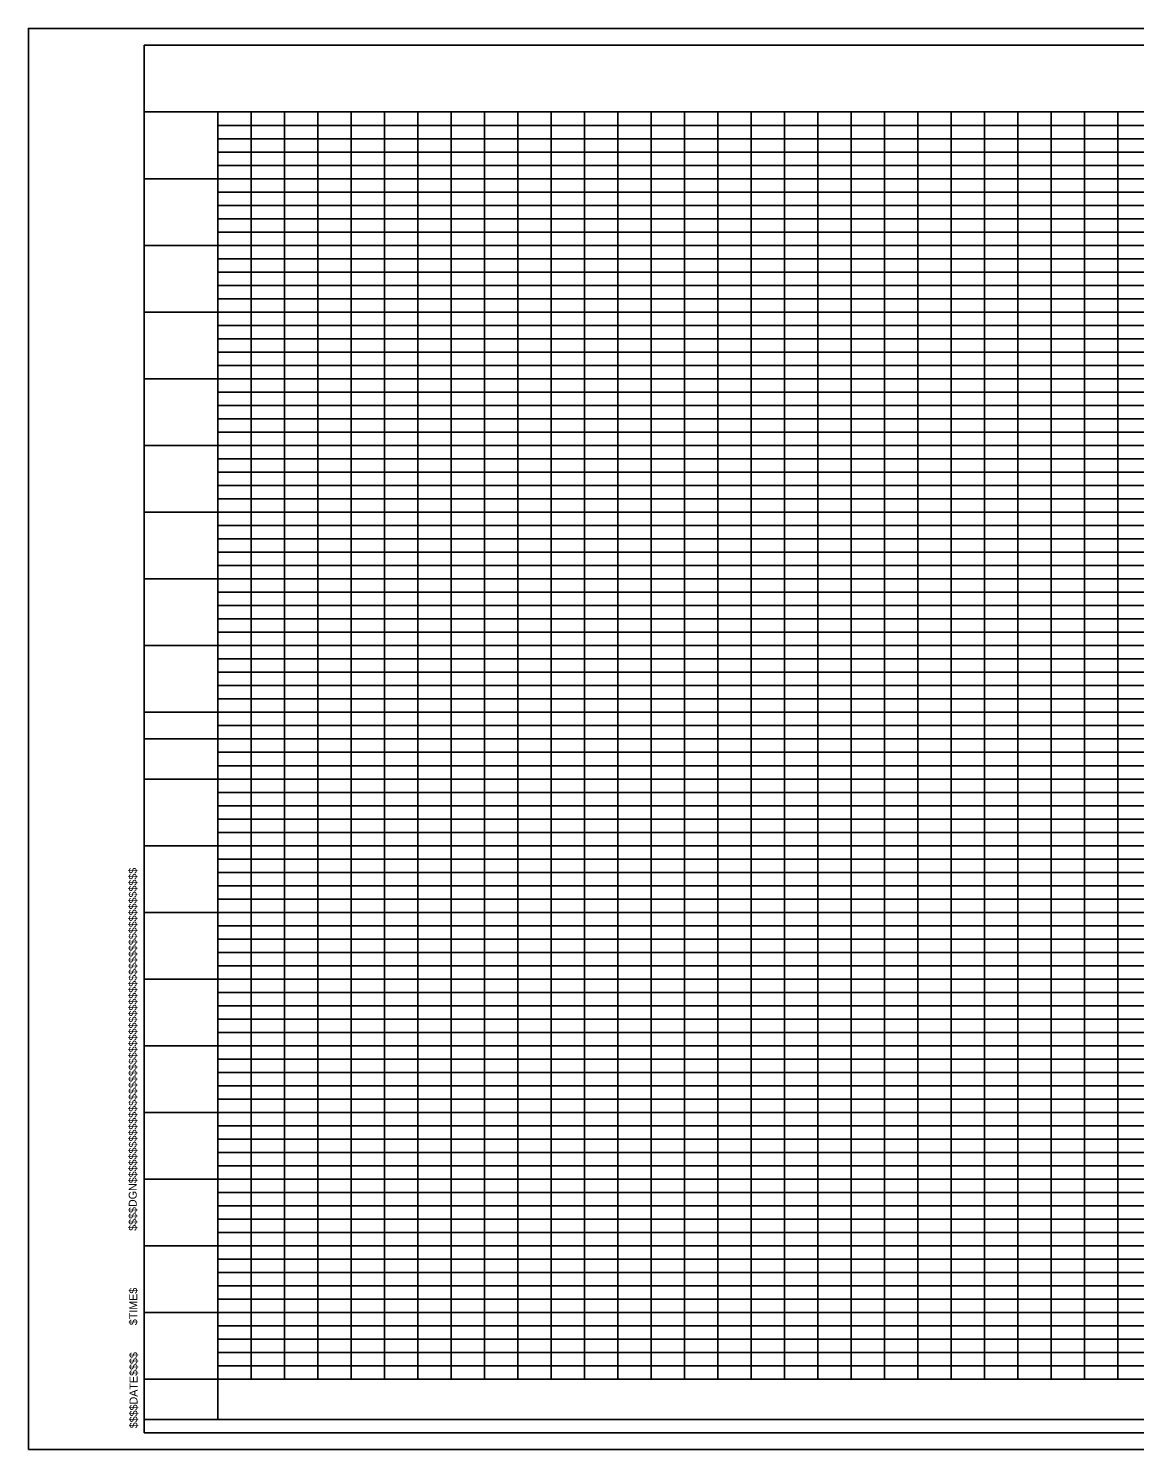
# Model space of a CAD drawing. Extents: x -87 to 2484, y -13 to 1056.
# Drawn here: x -87 to 742, y -13 to 1053 of the extents above; entities that cross this region are included whole.
import ezdxf

# ---------------------------------------------------------------- set-up
doc = ezdxf.new("R2010")
doc.units = 0
for name, color, linetype in [('D_CFL_Clip_Boundary_1', 7, 'Continuous'), ('D_CFL_Clip_Boundary_2', 7, 'Continuous'), ('D_CFL_Sheet_Border_ PlotShape', 7, 'Continuous'), ('D_CFL_Sheet_Border_Base', 7, 'Continuous'), ('D_CFL_Sheet_Border_Plan_Plan', 7, 'Continuous'), ('D_CFL_Sheet_Border_PnP', 7, 'Continuous'), ('D_CFL_Sheet_Border_Profile', 7, 'Continuous')]:
    doc.layers.add(name, color=color, linetype=linetype)

msp = doc.modelspace()

# ---------------------------------------------------------------- linework, layer by layer
at = {"layer": 'D_CFL_Clip_Boundary_1'}
msp.add_lwpolyline([(0, 520), (0, 1040), (1305, 1040), (1305, 1000), (1560, 1000), (1560, 520)], close=True, dxfattribs=at)
msp.add_lwpolyline([(0, 520), (0, 1040), (1305, 1040), (1305, 1000), (1560, 1000), (1560, 520)], close=True, dxfattribs=at)
at = {"layer": 'D_CFL_Clip_Boundary_2'}
msp.add_lwpolyline([(1505, 520), (55, 520), (55, 40), (1505, 40)], close=True, dxfattribs=at)
msp.add_lwpolyline([(1505, 520), (55, 520), (55, 40), (1505, 40)], close=True, dxfattribs=at)
at = {"layer": 'D_CFL_Sheet_Border_ PlotShape'}
msp.add_line((-86.9, -12.7), (-86.9, -12.7), dxfattribs=at)
msp.add_line((-86.9, -12.7), (-86.9, -12.7), dxfattribs=at)
msp.add_lwpolyline([(-86.9, -12.7), (1576.9, -12.7), (1576.9, 1052.6), (-86.9, 1052.6)], close=True, dxfattribs=at)
at = {"layer": 'D_CFL_Sheet_Border_Base'}
msp.add_lwpolyline([(0, 0), (1560, 0), (1560, 1040), (0, 1040)], close=True, dxfattribs=at)
msp.add_lwpolyline([(0, 0), (1560, 0), (1560, 1040), (0, 1040)], close=True, dxfattribs=at)
at = {"layer": 'D_CFL_Sheet_Border_Plan_Plan'}
msp.add_line((0, 520), (1560, 520), dxfattribs=at)
msp.add_line((0, 520), (1560, 520), dxfattribs=at)
at = {"layer": 'D_CFL_Sheet_Border_PnP'}
for p, q in [((0, 520), (1560, 520)), ((0, 520), (1560, 520)), ((55, 520), (55, 10)), ((55, 520), (55, 10)), ((80, 40), (80, 520)), ((80, 40), (80, 520)), ((105, 40), (105, 520)), ((105, 40), (105, 520)), ((130, 40), (130, 520)), ((130, 40), (130, 520)), ((155, 40), (155, 520)), ((155, 40), (155, 520)), ((180, 40), (180, 520)), ((180, 40), (180, 520)), ((205, 40), (205, 520)), ((205, 40), (205, 520)), ((230, 40), (230, 520)), ((230, 40), (230, 520)), ((255, 40), (255, 520)), ((255, 40), (255, 520)), ((280, 40), (280, 520)), ((280, 40), (280, 520)), ((305, 40), (305, 520)), ((305, 40), (305, 520)), ((330, 40), (330, 520)), ((330, 40), (330, 520)), ((355, 40), (355, 520)), ((355, 40), (355, 520)), ((380, 40), (380, 520)), ((380, 40), (380, 520)), ((405, 40), (405, 520)), ((405, 40), (405, 520)), ((430, 40), (430, 520)), ((430, 40), (430, 520)), ((455, 40), (455, 520)), ((455, 40), (455, 520)), ((480, 40), (480, 520)), ((480, 40), (480, 520)), ((505, 40), (505, 520)), ((505, 40), (505, 520)), ((530, 40), (530, 520)), ((530, 40), (530, 520)), ((555, 40), (555, 520)), ((555, 40), (555, 520)), ((580, 40), (580, 520)), ((580, 40), (580, 520)), ((605, 40), (605, 520)), ((605, 40), (605, 520)), ((630, 40), (630, 520)), ((630, 40), (630, 520)), ((655, 40), (655, 520)), ((655, 40), (655, 520)), ((680, 40), (680, 520)), ((680, 40), (680, 520)), ((705, 40), (705, 520)), ((705, 40), (705, 520)), ((730, 40), (730, 520)), ((730, 40), (730, 520)), ((55, 510), (1505, 510)), ((55, 510), (1505, 510)), ((55, 500), (1505, 500)), ((55, 500), (1505, 500)), ((55, 490), (0, 490)), ((55, 490), (0, 490)), ((55, 490), (1505, 490)), ((55, 490), (1505, 490)), ((55, 480), (1505, 480)), ((55, 480), (1505, 480)), ((55, 470), (1505, 470)), ((55, 470), (1505, 470)), ((55, 460), (1505, 460)), ((55, 460), (1505, 460)), ((55, 450), (1505, 450)), ((55, 450), (1505, 450)), ((55, 440), (0, 440)), ((55, 440), (0, 440)), ((55, 440), (1505, 440)), ((55, 440), (1505, 440)), ((55, 430), (1505, 430)), ((55, 430), (1505, 430)), ((55, 420), (1505, 420)), ((55, 420), (1505, 420)), ((55, 410), (1505, 410)), ((55, 410), (1505, 410)), ((55, 400), (1505, 400)), ((55, 400), (1505, 400)), ((55, 390), (0, 390)), ((55, 390), (0, 390)), ((55, 390), (1505, 390)), ((55, 390), (1505, 390)), ((55, 380), (1505, 380)), ((55, 380), (1505, 380)), ((55, 370), (1505, 370)), ((55, 370), (1505, 370)), ((55, 360), (1505, 360)), ((55, 360), (1505, 360)), ((55, 350), (1505, 350)), ((55, 350), (1505, 350)), ((55, 340), (0, 340)), ((55, 340), (0, 340)), ((55, 340), (1505, 340)), ((55, 340), (1505, 340)), ((55, 330), (1505, 330)), ((55, 330), (1505, 330)), ((55, 320), (1505, 320)), ((55, 320), (1505, 320)), ((55, 310), (1505, 310)), ((55, 310), (1505, 310)), ((55, 300), (1505, 300)), ((55, 300), (1505, 300)), ((55, 290), (0, 290)), ((55, 290), (0, 290)), ((55, 290), (1505, 290)), ((55, 290), (1505, 290)), ((55, 280), (1505, 280)), ((55, 280), (1505, 280)), ((55, 270), (1505, 270)), ((55, 270), (1505, 270)), ((55, 260), (1505, 260)), ((55, 260), (1505, 260)), ((55, 250), (1505, 250)), ((55, 250), (1505, 250)), ((55, 240), (0, 240)), ((55, 240), (0, 240)), ((55, 240), (1505, 240)), ((55, 240), (1505, 240)), ((55, 230), (1505, 230)), ((55, 230), (1505, 230)), ((55, 220), (1505, 220)), ((55, 220), (1505, 220)), ((55, 210), (1505, 210)), ((55, 210), (1505, 210)), ((55, 200), (1505, 200)), ((55, 200), (1505, 200)), ((55, 190), (0, 190)), ((55, 190), (0, 190)), ((55, 190), (1505, 190)), ((55, 190), (1505, 190)), ((55, 180), (1505, 180)), ((55, 180), (1505, 180)), ((55, 170), (1505, 170)), ((55, 170), (1505, 170)), ((55, 160), (1505, 160)), ((55, 160), (1505, 160)), ((55, 150), (1505, 150)), ((55, 150), (1505, 150)), ((55, 140), (0, 140)), ((55, 140), (0, 140)), ((55, 140), (1505, 140)), ((55, 140), (1505, 140)), ((55, 130), (1505, 130)), ((55, 130), (1505, 130)), ((55, 120), (1505, 120)), ((55, 120), (1505, 120)), ((55, 110), (1505, 110)), ((55, 110), (1505, 110)), ((55, 100), (1505, 100)), ((55, 100), (1505, 100)), ((55, 90), (0, 90)), ((55, 90), (0, 90)), ((55, 90), (1505, 90)), ((55, 90), (1505, 90)), ((55, 80), (1505, 80)), ((55, 80), (1505, 80)), ((55, 70), (1505, 70)), ((55, 70), (1505, 70)), ((55, 60), (1505, 60)), ((55, 60), (1505, 60)), ((55, 50), (1505, 50)), ((55, 50), (1505, 50)), ((55, 40), (0, 40)), ((55, 40), (0, 40)), ((55, 40), (1505, 40)), ((55, 40), (1505, 40)), ((0, 10), (1560, 10)), ((0, 10), (1560, 10))]:
    msp.add_line(p, q, dxfattribs=at)
at = {"layer": 'D_CFL_Sheet_Border_Profile'}
for p, q in [((0, 990), (1560, 990)), ((0, 990), (1560, 990)), ((55, 990), (55, 10)), ((55, 990), (55, 10)), ((80, 40), (80, 990)), ((80, 40), (80, 990)), ((105, 40), (105, 990)), ((105, 40), (105, 990)), ((130, 40), (130, 990)), ((130, 40), (130, 990)), ((155, 40), (155, 990)), ((155, 40), (155, 990)), ((180, 40), (180, 990)), ((180, 40), (180, 990)), ((205, 40), (205, 990)), ((205, 40), (205, 990)), ((230, 40), (230, 990)), ((230, 40), (230, 990)), ((255, 40), (255, 990)), ((255, 40), (255, 990)), ((280, 40), (280, 990)), ((280, 40), (280, 990)), ((305, 40), (305, 990)), ((305, 40), (305, 990)), ((330, 40), (330, 990)), ((330, 40), (330, 990)), ((355, 40), (355, 990)), ((355, 40), (355, 990)), ((380, 40), (380, 990)), ((380, 40), (380, 990)), ((405, 40), (405, 990)), ((405, 40), (405, 990)), ((430, 40), (430, 990)), ((430, 40), (430, 990)), ((455, 40), (455, 990)), ((455, 40), (455, 990)), ((480, 40), (480, 990)), ((480, 40), (480, 990)), ((505, 40), (505, 990)), ((505, 40), (505, 990)), ((530, 40), (530, 990)), ((530, 40), (530, 990)), ((555, 40), (555, 990)), ((555, 40), (555, 990)), ((580, 40), (580, 990)), ((580, 40), (580, 990)), ((605, 40), (605, 990)), ((605, 40), (605, 990)), ((630, 40), (630, 990)), ((630, 40), (630, 990)), ((655, 40), (655, 990)), ((655, 40), (655, 990)), ((680, 40), (680, 990)), ((680, 40), (680, 990)), ((705, 40), (705, 990)), ((705, 40), (705, 990)), ((730, 40), (730, 990)), ((730, 40), (730, 990)), ((55, 980), (1505, 980)), ((55, 980), (1505, 980)), ((55, 970), (1505, 970)), ((55, 970), (1505, 970)), ((55, 960), (1505, 960)), ((55, 960), (1505, 960)), ((55, 950), (1505, 950)), ((55, 950), (1505, 950)), ((55, 940), (0, 940)), ((55, 940), (0, 940)), ((55, 940), (1505, 940)), ((55, 940), (1505, 940)), ((55, 930), (1505, 930)), ((55, 930), (1505, 930)), ((55, 920), (1505, 920)), ((55, 920), (1505, 920)), ((55, 910), (1505, 910)), ((55, 910), (1505, 910)), ((55, 900), (1505, 900)), ((55, 900), (1505, 900)), ((55, 890), (0, 890)), ((55, 890), (0, 890)), ((55, 890), (1505, 890)), ((55, 890), (1505, 890)), ((55, 880), (1505, 880)), ((55, 880), (1505, 880)), ((55, 870), (1505, 870)), ((55, 870), (1505, 870)), ((55, 860), (1505, 860)), ((55, 860), (1505, 860)), ((55, 850), (1505, 850)), ((55, 850), (1505, 850)), ((55, 840), (0, 840)), ((55, 840), (0, 840)), ((55, 840), (1505, 840)), ((55, 840), (1505, 840)), ((55, 830), (1505, 830)), ((55, 830), (1505, 830)), ((55, 820), (1505, 820)), ((55, 820), (1505, 820)), ((55, 810), (1505, 810)), ((55, 810), (1505, 810)), ((55, 800), (1505, 800)), ((55, 800), (1505, 800)), ((55, 790), (0, 790)), ((55, 790), (0, 790)), ((55, 790), (1505, 790)), ((55, 790), (1505, 790)), ((55, 780), (1505, 780)), ((55, 780), (1505, 780)), ((55, 770), (1505, 770)), ((55, 770), (1505, 770)), ((55, 760), (1505, 760)), ((55, 760), (1505, 760)), ((55, 750), (1505, 750)), ((55, 750), (1505, 750)), ((55, 740), (0, 740)), ((55, 740), (0, 740)), ((55, 740), (1505, 740)), ((55, 740), (1505, 740)), ((55, 730), (1505, 730)), ((55, 730), (1505, 730)), ((55, 720), (1505, 720)), ((55, 720), (1505, 720)), ((55, 710), (1505, 710)), ((55, 710), (1505, 710)), ((55, 700), (1505, 700)), ((55, 700), (1505, 700)), ((55, 690), (0, 690)), ((55, 690), (0, 690)), ((55, 690), (1505, 690)), ((55, 690), (1505, 690)), ((55, 680), (1505, 680)), ((55, 680), (1505, 680)), ((55, 670), (1505, 670)), ((55, 670), (1505, 670)), ((55, 660), (1505, 660)), ((55, 660), (1505, 660)), ((55, 650), (1505, 650)), ((55, 650), (1505, 650)), ((55, 640), (0, 640)), ((55, 640), (0, 640)), ((55, 640), (1505, 640)), ((55, 640), (1505, 640)), ((55, 630), (1505, 630)), ((55, 630), (1505, 630)), ((55, 620), (1505, 620)), ((55, 620), (1505, 620)), ((55, 610), (1505, 610)), ((55, 610), (1505, 610)), ((55, 600), (1505, 600)), ((55, 600), (1505, 600)), ((55, 590), (0, 590)), ((55, 590), (0, 590)), ((55, 590), (1505, 590)), ((55, 590), (1505, 590)), ((55, 580), (1505, 580)), ((55, 580), (1505, 580)), ((55, 570), (1505, 570)), ((55, 570), (1505, 570)), ((55, 560), (1505, 560)), ((55, 560), (1505, 560)), ((55, 550), (1505, 550)), ((55, 550), (1505, 550)), ((55, 540), (0, 540)), ((55, 540), (0, 540)), ((55, 540), (1505, 540)), ((55, 540), (1505, 540)), ((55, 530), (1505, 530)), ((55, 530), (1505, 530)), ((55, 520), (1505, 520)), ((55, 520), (1505, 520)), ((55, 510), (1505, 510)), ((55, 510), (1505, 510)), ((55, 500), (1505, 500)), ((55, 500), (1505, 500)), ((55, 490), (0, 490)), ((55, 490), (0, 490)), ((55, 490), (1505, 490)), ((55, 490), (1505, 490)), ((55, 480), (1505, 480)), ((55, 480), (1505, 480)), ((55, 470), (1505, 470)), ((55, 470), (1505, 470)), ((55, 460), (1505, 460)), ((55, 460), (1505, 460)), ((55, 450), (1505, 450)), ((55, 450), (1505, 450)), ((55, 440), (0, 440)), ((55, 440), (0, 440)), ((55, 440), (1505, 440)), ((55, 440), (1505, 440)), ((55, 430), (1505, 430)), ((55, 430), (1505, 430)), ((55, 420), (1505, 420)), ((55, 420), (1505, 420)), ((55, 410), (1505, 410)), ((55, 410), (1505, 410)), ((55, 400), (1505, 400)), ((55, 400), (1505, 400)), ((55, 390), (0, 390)), ((55, 390), (0, 390)), ((55, 390), (1505, 390)), ((55, 390), (1505, 390)), ((55, 380), (1505, 380)), ((55, 380), (1505, 380)), ((55, 370), (1505, 370)), ((55, 370), (1505, 370)), ((55, 360), (1505, 360)), ((55, 360), (1505, 360)), ((55, 350), (1505, 350)), ((55, 350), (1505, 350)), ((55, 340), (0, 340)), ((55, 340), (0, 340)), ((55, 340), (1505, 340)), ((55, 340), (1505, 340)), ((55, 330), (1505, 330)), ((55, 330), (1505, 330)), ((55, 320), (1505, 320)), ((55, 320), (1505, 320)), ((55, 310), (1505, 310)), ((55, 310), (1505, 310)), ((55, 300), (1505, 300)), ((55, 300), (1505, 300)), ((55, 290), (0, 290)), ((55, 290), (0, 290)), ((55, 290), (1505, 290)), ((55, 290), (1505, 290)), ((55, 280), (1505, 280)), ((55, 280), (1505, 280)), ((55, 270), (1505, 270)), ((55, 270), (1505, 270)), ((55, 260), (1505, 260)), ((55, 260), (1505, 260)), ((55, 250), (1505, 250)), ((55, 250), (1505, 250)), ((55, 240), (0, 240)), ((55, 240), (0, 240)), ((55, 240), (1505, 240)), ((55, 240), (1505, 240)), ((55, 230), (1505, 230)), ((55, 230), (1505, 230)), ((55, 220), (1505, 220)), ((55, 220), (1505, 220)), ((55, 210), (1505, 210)), ((55, 210), (1505, 210)), ((55, 200), (1505, 200)), ((55, 200), (1505, 200)), ((55, 190), (0, 190)), ((55, 190), (0, 190)), ((55, 190), (1505, 190)), ((55, 190), (1505, 190)), ((55, 180), (1505, 180)), ((55, 180), (1505, 180)), ((55, 170), (1505, 170)), ((55, 170), (1505, 170)), ((55, 160), (1505, 160)), ((55, 160), (1505, 160)), ((55, 150), (1505, 150)), ((55, 150), (1505, 150)), ((55, 140), (0, 140)), ((55, 140), (0, 140)), ((55, 140), (1505, 140)), ((55, 140), (1505, 140)), ((55, 130), (1505, 130)), ((55, 130), (1505, 130)), ((55, 120), (1505, 120)), ((55, 120), (1505, 120)), ((55, 110), (1505, 110)), ((55, 110), (1505, 110)), ((55, 100), (1505, 100)), ((55, 100), (1505, 100)), ((55, 90), (0, 90)), ((55, 90), (0, 90)), ((55, 90), (1505, 90)), ((55, 90), (1505, 90)), ((55, 80), (1505, 80)), ((55, 80), (1505, 80)), ((55, 70), (1505, 70)), ((55, 70), (1505, 70)), ((55, 60), (1505, 60)), ((55, 60), (1505, 60)), ((55, 50), (1505, 50)), ((55, 50), (1505, 50)), ((55, 40), (0, 40)), ((55, 40), (0, 40)), ((55, 40), (1505, 40)), ((55, 40), (1505, 40)), ((0, 10), (1560, 10)), ((0, 10), (1560, 10))]:
    msp.add_line(p, q, dxfattribs=at)

# ---------------------------------------------------------------- texts
at = {"layer": 'D_CFL_Sheet_Border_Base'}
for s, p in [('$$$$DGN$$$$$$$$$$$$$$$$$$$$$$$$$$$$$$$$$$$$$$$$$$$$$$$$$$$$$', (-5.7, 151.3)), ('$$$$DGN$$$$$$$$$$$$$$$$$$$$$$$$$$$$$$$$$$$$$$$$$$$$$$$$$$$$$', (-5.7, 151.3)), ('$TIME$', (-5.3, 80.6)), ('$TIME$', (-5.3, 80.6)), ('$$$$DATE$$$$', (-5.1, 3.3)), ('$$$$DATE$$$$', (-5.1, 3.3))]:
    msp.add_text(s, height=6, rotation=90, dxfattribs=at).set_placement(p)

doc.saveas('drawing.dxf')
